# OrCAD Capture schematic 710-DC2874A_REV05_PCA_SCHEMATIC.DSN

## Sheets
1 PAGE4: company: ANALOG DEVICES; note: DEMO BOARD BILL OF MATERIALS; note: 5V, MULTI-PHASE SILENT SWITCHER 2
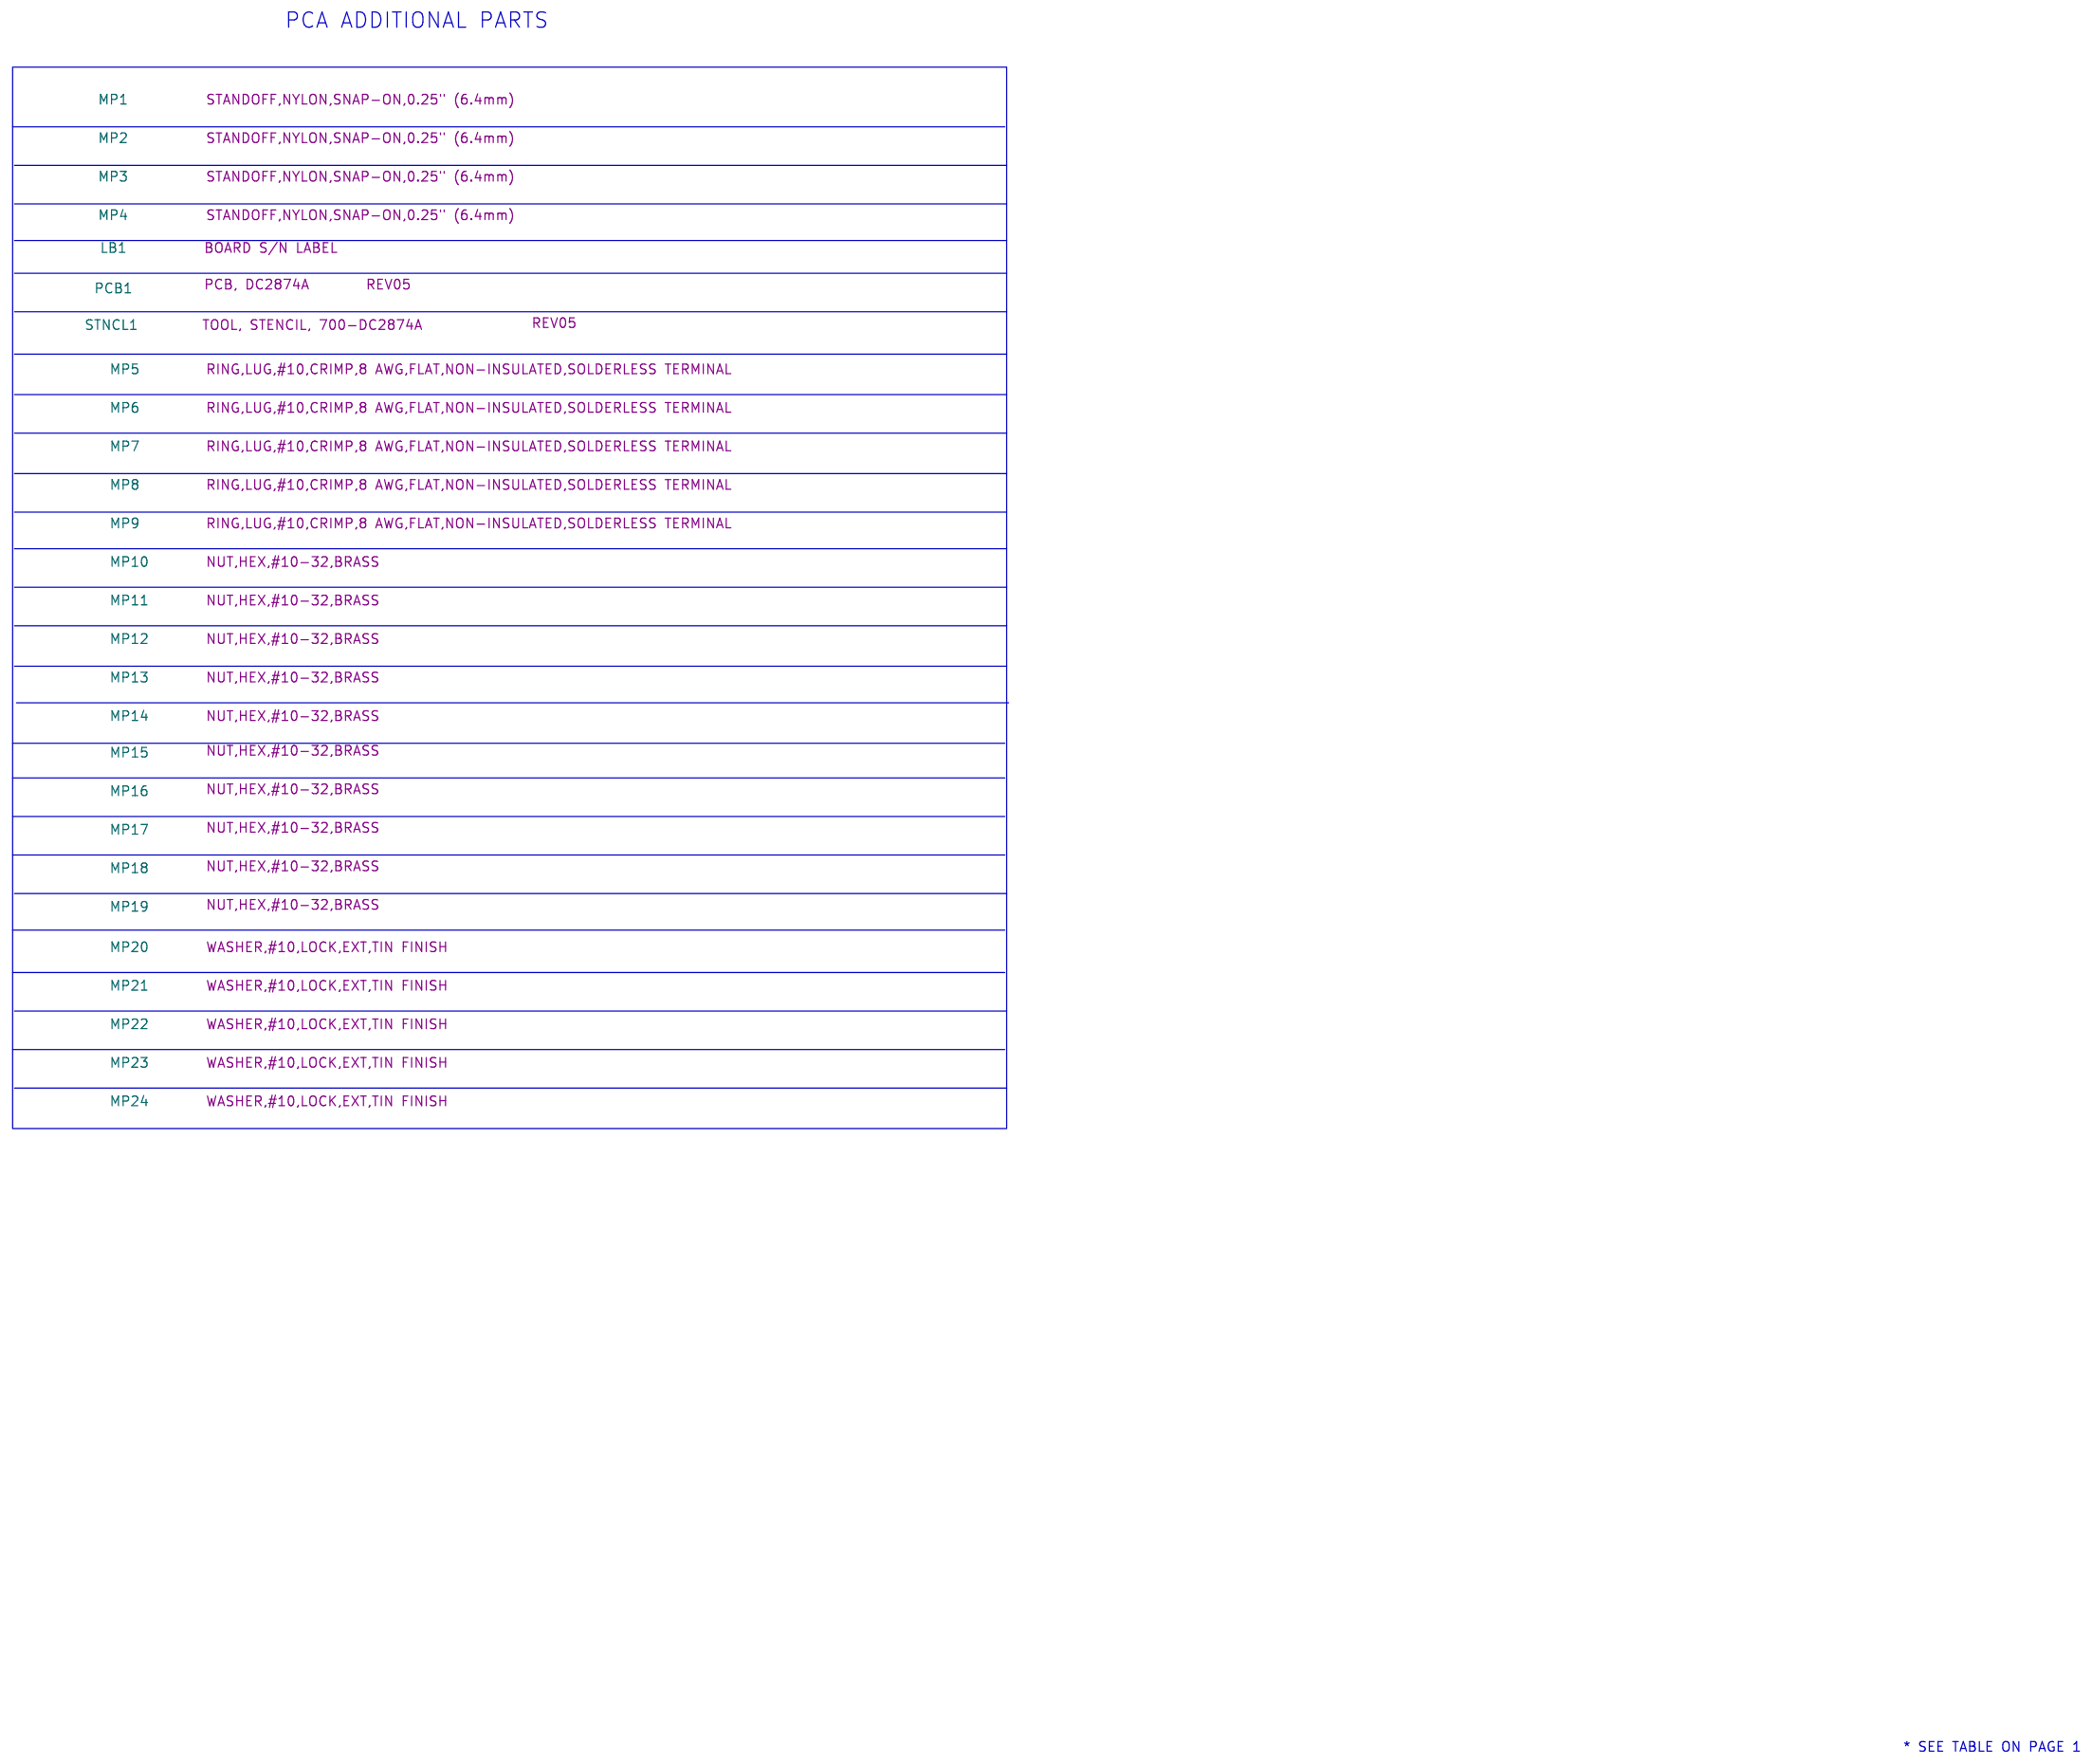
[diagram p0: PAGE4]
2 PAGE3: size B
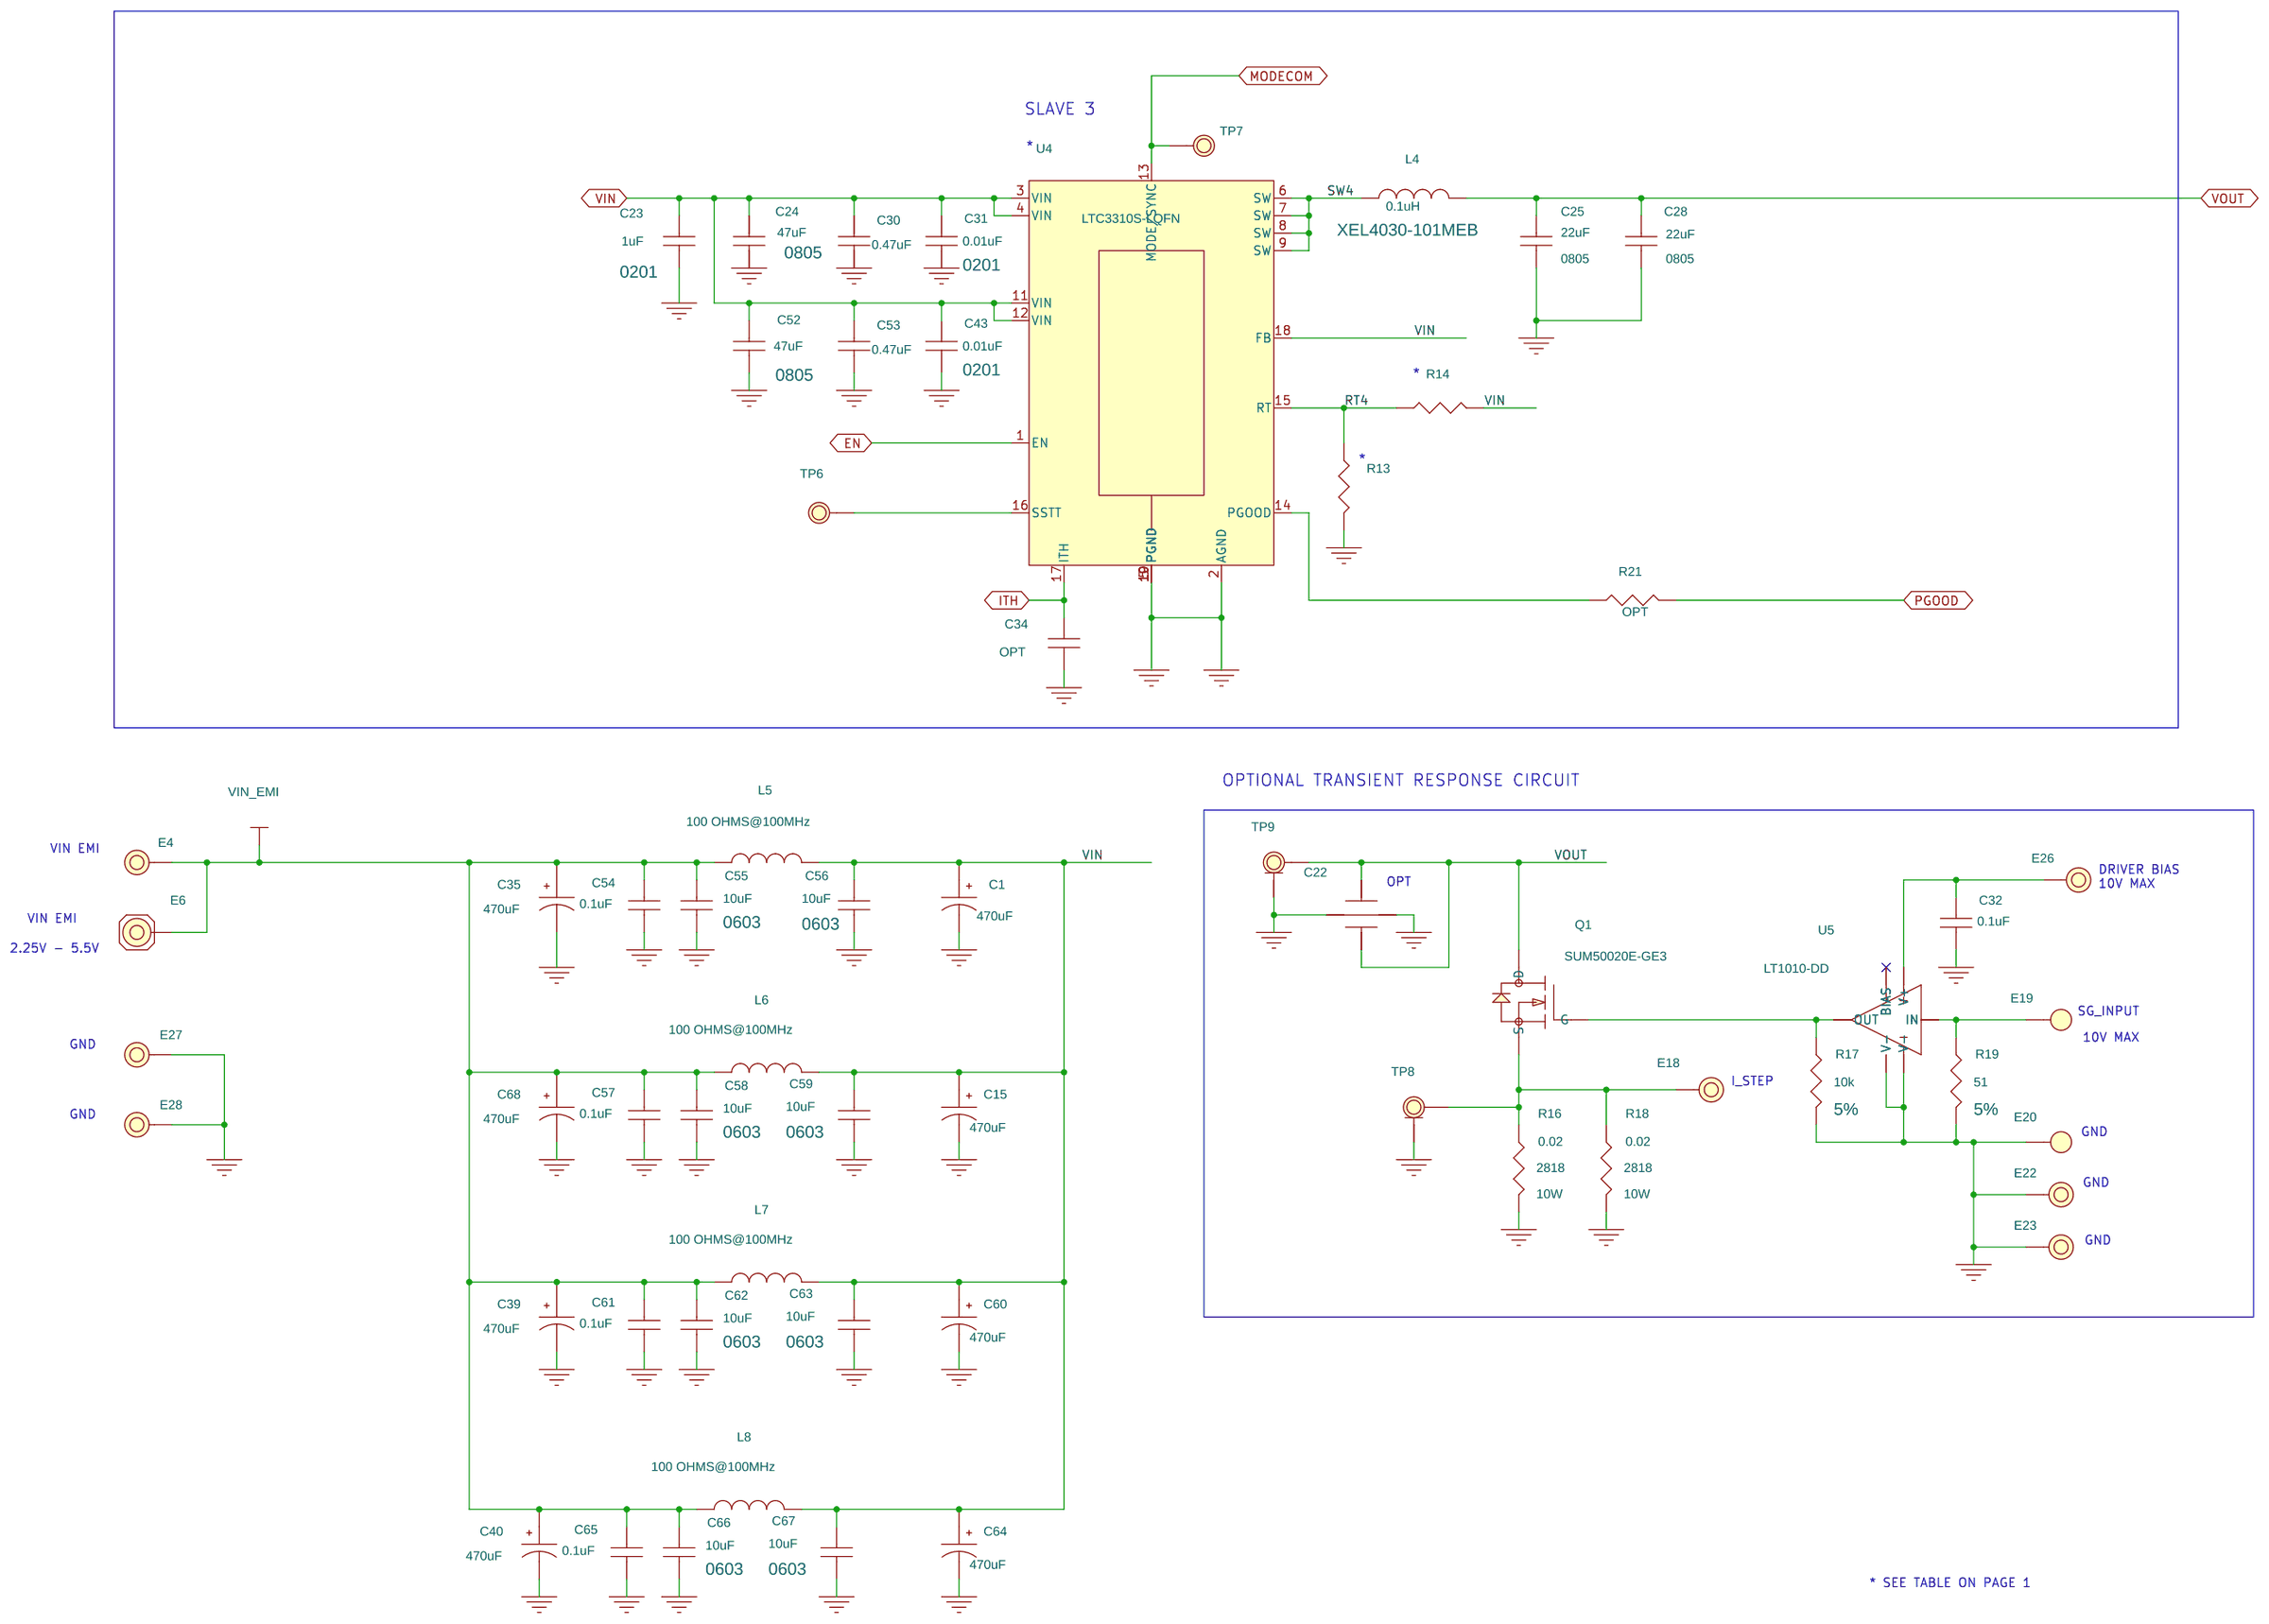
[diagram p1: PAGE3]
3 PAGE2: size B
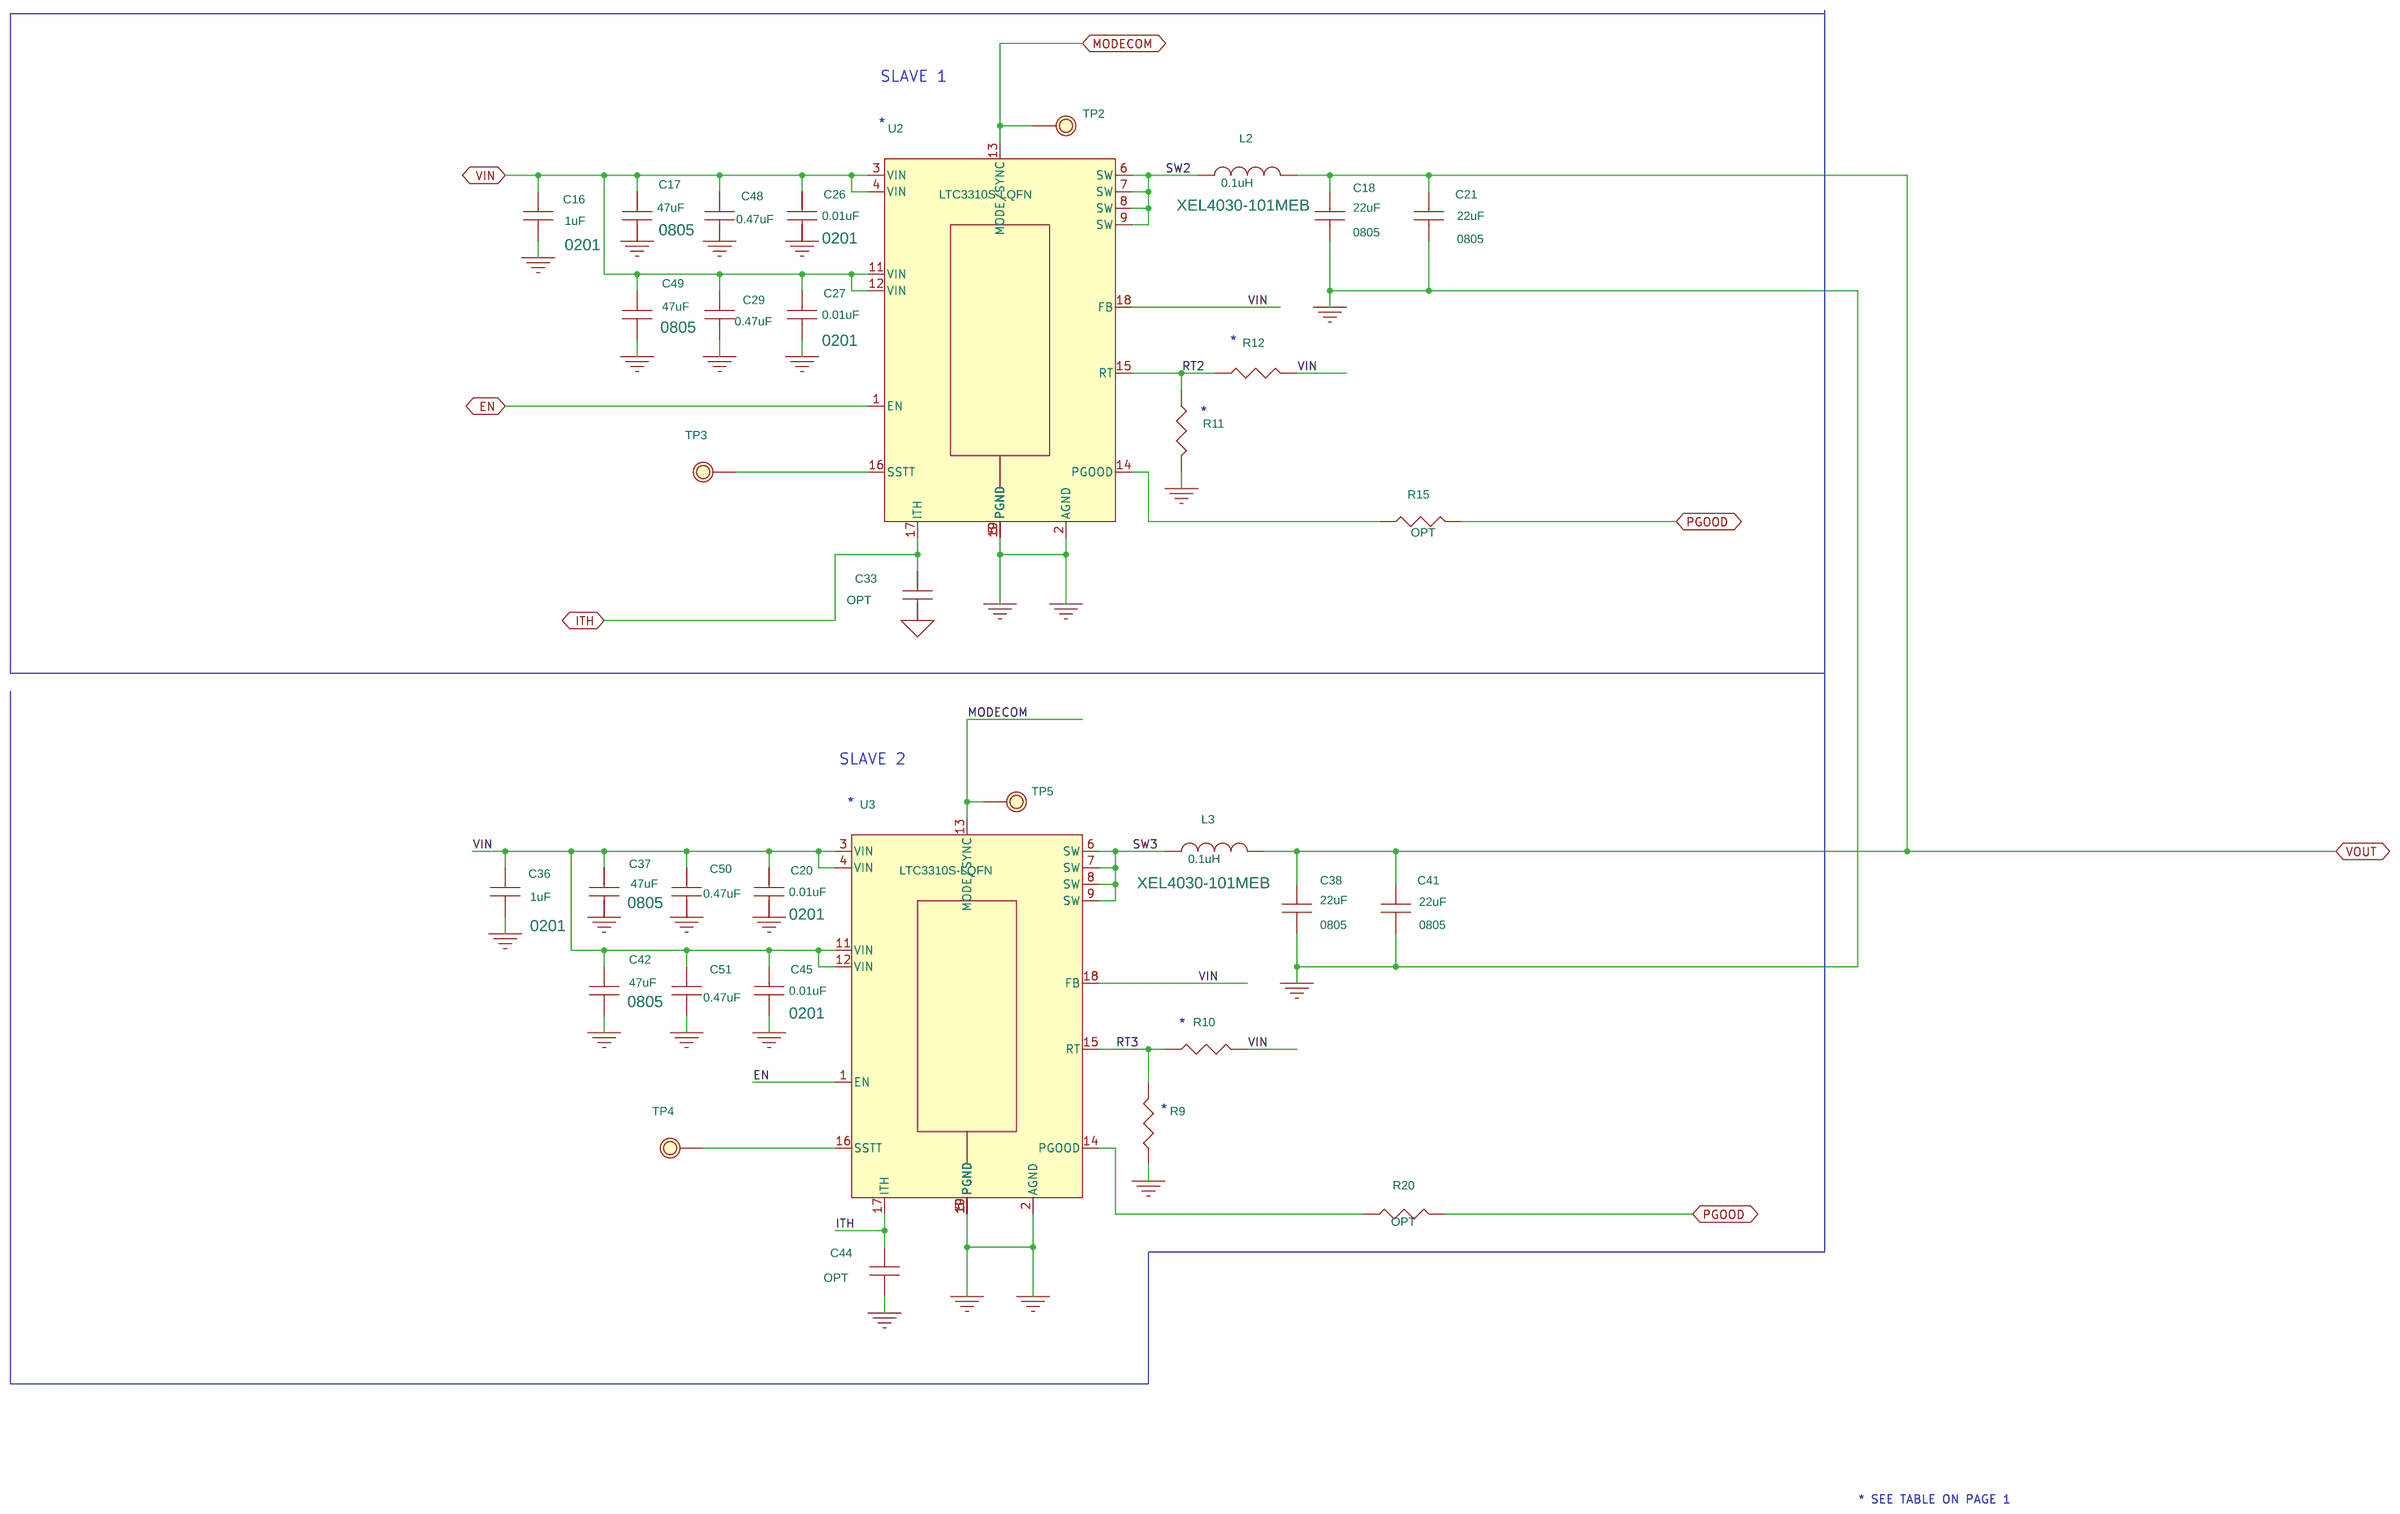
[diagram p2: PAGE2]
4 PAGE1: size B
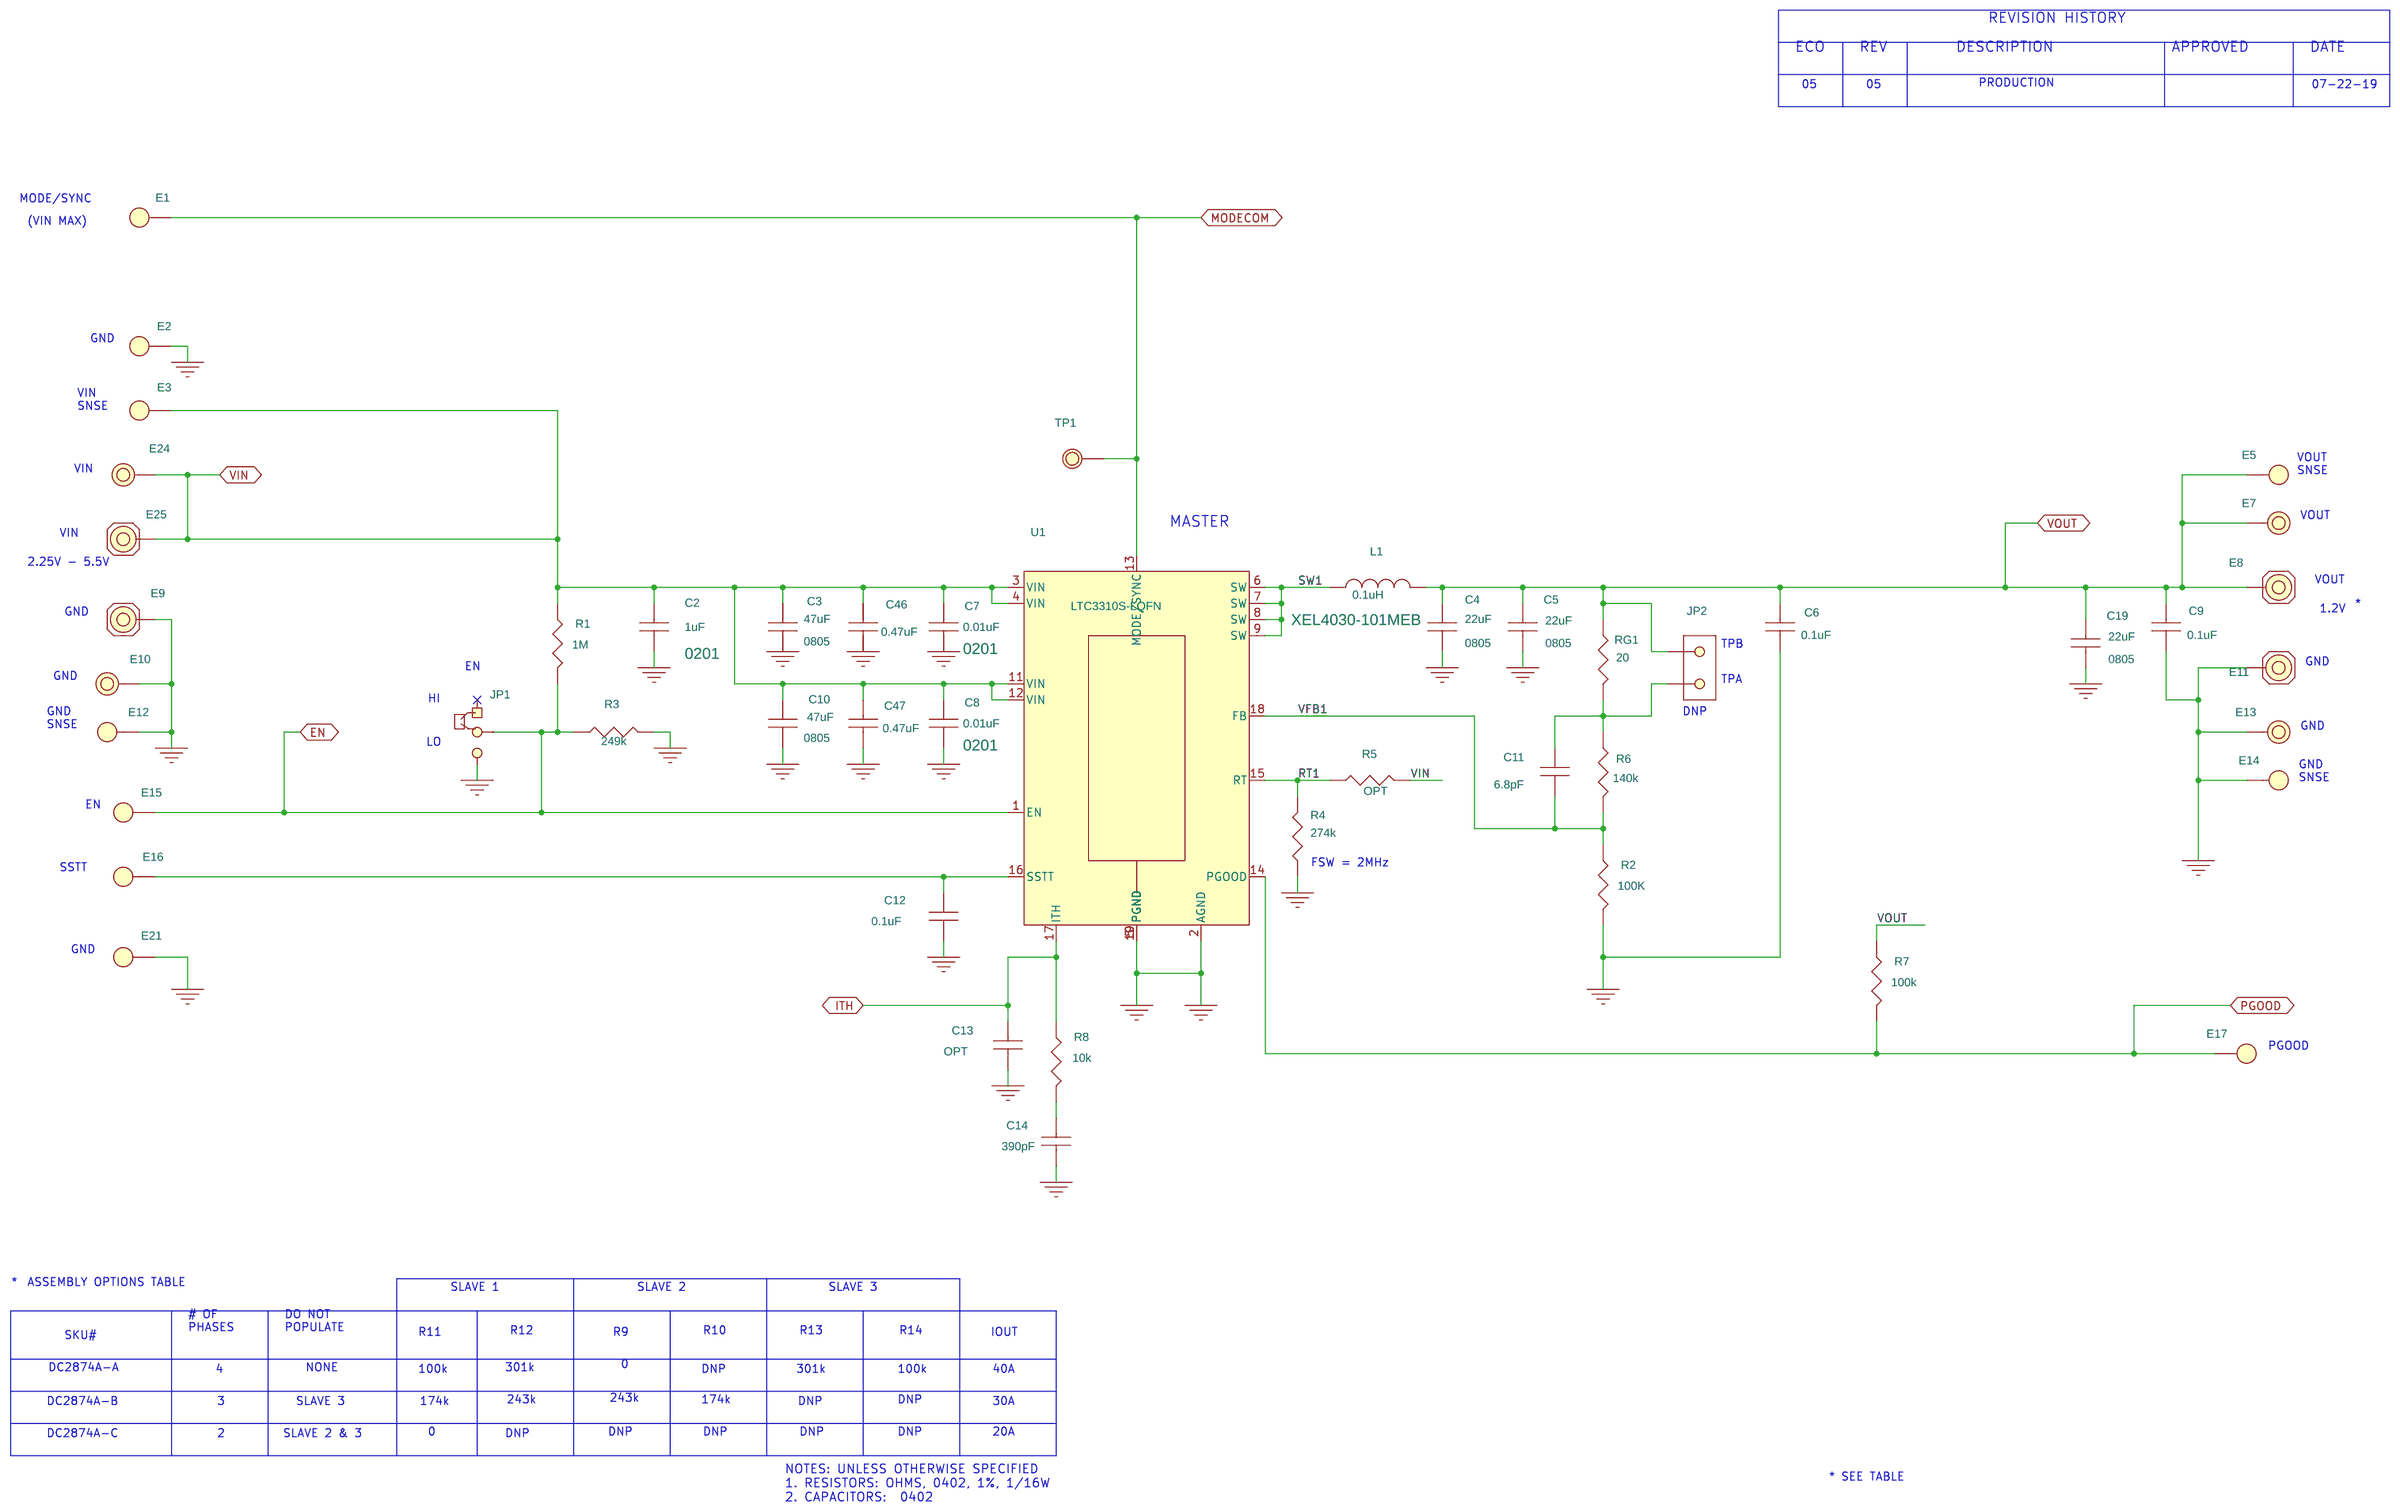
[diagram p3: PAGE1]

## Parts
sheet PAGE1
C2  1uF  [CC0201M]
C3  47uF  [CC0805N]
C4  22uF  [CC0805N]
C5  22uF  [CC0805N]
C6  0.1uF  [CC0402N]
C7  0.01uF  [CC0201M]
C8  0.01uF  [CC0201M]
C9  0.1uF  [CC0402N]
C10  47uF  [CC0805N]
C11  6.8pF  [CC0402N]
C12  0.1uF  [CC0402N]
C13  OPT  [CC0402N]
C14  390pF  [CC0402N]
C19  22uF  [CC0805N]
C46  0.47uF  [CC0402N]
C47  0.47uF  [CC0402N]
E1  TEST POINT  [MILLMAX2308]
E2  TEST POINT  [MILLMAX2308]
E3  TEST POINT  [MILLMAX2308]
E5  TEST POINT  [MILLMAX2308]
E7  TEST POINT  [MILLMAX2501]
E8  STUD  [PENN-KFH-032]
E9  STUD  [PENN-KFH-032]
E10  TEST POINT  [MILLMAX2501]
E11  STUD  [PENN-KFH-032]
E12  TEST POINT  [MILLMAX2308]
E13  TEST POINT  [MILLMAX2501]
E14  TEST POINT  [MILLMAX2308]
E15  TEST POINT  [MILLMAX2308]
E16  TEST POINT  [MILLMAX2308]
E17  TEST POINT  [MILLMAX2308]
E21  TEST POINT  [MILLMAX2308]
E24  TEST POINT  [MILLMAX2501]
E25  STUD  [PENN-KFH-032]
JP1  HDR  [HD1X3-079]
JP2  HDR  [HD1X2-079]
L1  0.1uH  [COILCRAFT-XEL4030]
R1  1M  [CR0402N]
R2  100K  [CR0402N]
R3  249k  [CR0402N]
R4  274k  [CR0402N]
R5  OPT  [CR0402N]
R6  140k  [CR0402N]
R7  100k  [CR0402N]
R8  10k  [CR0402N]
RG1  20  [CR0402N]
TP1  TEST PAD  [PADSTYLE2]
U1  LTC3310S-LQFN  [LTC-LQFN-18-1548]
XJP1  SHUNT
sheet PAGE2
C16  1uF  [CC0201M]
C17  47uF  [CC0805N]
C18  22uF  [CC0805N]
C20  0.01uF  [CC0201M]
C21  22uF  [CC0805N]
C26  0.01uF  [CC0201M]
C27  0.01uF  [CC0201M]
C29  0.47uF  [CC0402N]
C33  OPT  [CC0402N]
C36  1uF  [CC0201M]
C37  47uF  [CC0805N]
C38  22uF  [CC0805N]
C41  22uF  [CC0805N]
C42  47uF  [CC0805N]
C44  OPT  [CC0402N]
C45  0.01uF  [CC0201M]
C48  0.47uF  [CC0402N]
C49  47uF  [CC0805N]
C50  0.47uF  [CC0402N]
C51  0.47uF  [CC0402N]
L2  0.1uH  [COILCRAFT-XEL4030]
L3  0.1uH  [COILCRAFT-XEL4030]
R9  0  [CR0402N]
R10  OPT  [CR0402N]
R11  100K  [CR0402N]
R12  301k  [CR0402N]
R15  OPT  [CR0402N]
R20  OPT  [CR0402N]
TP2  TEST PAD  [PADSTYLE2]
TP3  TEST PAD  [PADSTYLE2]
TP4  TEST PAD  [PADSTYLE2]
TP5  TEST PAD  [PADSTYLE2]
U2  LTC3310S-LQFN  [LTC-LQFN-18-1548]
U3  LTC3310S-LQFN  [LTC-LQFN-18-1548]
sheet PAGE3
C1  470uF  [CAPMP7343N]
C15  470uF  [CAPMP7343N]
C22  1000pF  [JOHANSON-X2Y-X07]
C23  1uF  [CC0201M]
C24  47uF  [CC0805N]
C25  22uF  [CC0805N]
C28  22uF  [CC0805N]
C30  0.47uF  [CC0402N]
C31  0.01uF  [CC0201M]
C32  0.1uF  [CC0402N]
C34  OPT  [CC0402N]
C35  470uF  [CAPMP7343N]
C39  470uF  [CAPMP7343N]
C40  470uF  [CAPMP7343N]
C43  0.01uF  [CC0201M]
C52  47uF  [CC0805N]
C53  0.47uF  [CC0402N]
C54  0.1uF  [CC0402N]
C55  10uF  [CC0603N]
C56  10uF  [CC0603N]
C57  0.1uF  [CC0402N]
C58  10uF  [CC0603N]
C59  10uF  [CC0603N]
C60  470uF  [CAPMP7343N]
C61  0.1uF  [CC0402N]
C62  10uF  [CC0603N]
C63  10uF  [CC0603N]
C64  470uF  [CAPMP7343N]
C65  0.1uF  [CC0402N]
C66  10uF  [CC0603N]
C67  10uF  [CC0603N]
C68  470uF  [CAPMP7343N]
E4  TEST POINT  [MILLMAX2501]
E6  STUD  [PENN-KFH-032]
E18  TEST POINT  [MILLMAX2501]
E19  TEST POINT  [MILLMAX2308]
E20  TEST POINT  [MILLMAX2308]
E22  TEST POINT  [MILLMAX2501]
E23  TEST POINT  [MILLMAX2501]
E26  TEST POINT  [MILLMAX2501]
E27  TEST POINT  [MILLMAX2501]
E28  TEST POINT  [MILLMAX2501]
L4  0.1uH  [COILCRAFT-XEL4030]
L5  100 OHMS@100MHz  [WURTH-74279226101]
L6  100 OHMS@100MHz  [WURTH-74279226101]
L7  100 OHMS@100MHz  [WURTH-74279226101]
L8  100 OHMS@100MHz  [WURTH-74279226101]
Q1  SUM50020E-GE3  [VISHAY-TO-263-3]
R13  301k  [CR0402N]
R14  100K  [CR0402N]
R16  0.02  [VISHAY-WSHP2818]
R17  10k  [CR0402N]
R18  0.02  [VISHAY-WSHP2818]
R19  51  [CR0402N]
R21  OPT  [CR0402N]
TP6  TEST PAD  [PADSTYLE2]
TP7  TEST PAD  [PADSTYLE2]
TP8  TEST JACK  [HODEN-PA-652_ALT1]
TP9  TEST JACK  [HODEN-PA-652_ALT1]
U4  LTC3310S-LQFN  [LTC-LQFN-18-1548]
U5  LT1010-DD  [LTC-DD-8-1698]
sheet PAGE4
LB1  LABEL  [895-0154_REV01]
MP1  STANDOFF  [KEYSTONE_8829-8834]
MP2  STANDOFF  [KEYSTONE_8829-8834]
MP3  STANDOFF  [KEYSTONE_8829-8834]
MP4  STANDOFF  [KEYSTONE_8829-8834]
MP5  RING,LUG,#10,CRIMP  [UNASSIGNED]
MP6  RING,LUG,#10,CRIMP  [UNASSIGNED]
MP7  RING,LUG,#10,CRIMP  [UNASSIGNED]
MP8  RING,LUG,#10,CRIMP  [UNASSIGNED]
MP9  RING,LUG,#10,CRIMP  [UNASSIGNED]
MP10  NUT,HEX
MP11  NUT,HEX
MP12  NUT,HEX
MP13  NUT,HEX
MP14  NUT,HEX
MP15  NUT,HEX
MP16  NUT,HEX
MP17  NUT,HEX
MP18  NUT,HEX
MP19  NUT,HEX
MP20  WASHER
MP21  WASHER
MP22  WASHER
MP23  WASHER
MP24  WASHER
PCB1  PCB, DC2874A
STNCL1  TOOL, STENCIL, 700-DC2874A

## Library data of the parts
C2 C16 C23 C36 = CAP: CAP.,1uF,X6S,6.3V,20%,0201; CLASS: DISCRETE; Dielectric Type: X6S; FPLIST: CC0201N,CC0201L,CC0201M; Inventory Qty: 44100; Manufacturer: MURATA; Manufacturer PN: GRM033C80J105ME05D; PART_NUMBER: 150-0777; Package Size: 0201; Rated Voltage: 6.3V; Temperature Coefficient: X6S; Tolerance: 20%
C3 C10 C17 C24 C37 C42 C49 C52 = CAP: CAP.,47uF,X5R,10V,20%,0805; CLASS: DISCRETE; Dielectric Type: X5R; FPLIST: CC0805N,CC0805L,CC0805M; Inventory Qty: 9160; Manufacturer: MURATA; Manufacturer PN: GRM21BR61A476ME15L; PART_NUMBER: 150-0744; Package Size: 0805; Rated Voltage: 10V; Tolerance: 20%
C4 C5 C18 C19 C21 C25 C28 C38 C41 = CAP: CAP.,22uF,X5R,25V,20%,0805; CLASS: DISCRETE; Dielectric Type: X5R; FPLIST: CC0805N,CC0805L,CC0805M; Inventory Qty: 12704; Manufacturer: AVX; Manufacturer PN: 08053D226MAT2A; PART_NUMBER: 150-0068; Package Size: 0805; Rated Voltage: 25V; Tolerance: 20%
C6 C9 C12 C32 C54 C57 C61 C65 = CAP: CAP.,0.1uF,X5R,25V,10%,0402; CLASS: DISCRETE; Dielectric Type: X5R; FPLIST: CC0402N,CC0402L,CC0402M; Inventory Qty: 69552; Manufacturer: AVX; Manufacturer PN: 04023D104KAT2A; PART_NUMBER: 150-0249; Package Size: 0402; Rated Voltage: 25V; Tolerance: 10%
C7 C8 C20 C26 C27 C31 C43 C45 = CAP: CAP.,0.01uF,X7R,6.3V,10%,0201; CLASS: DISCRETE; Dielectric Type: X7R; Inventory Qty: 30155; Manufacturer: MURATA; Manufacturer PN: GRM033R70J103KA01D; PART_NUMBER: 150-0377; Package Size: 0201; Rated Voltage: 6.3V; Tolerance: 10%
C11 = CAP: CAP.,6.8pF,C0G/NP0,50V,+/-0.5pF,0402; CLASS: DISCRETE; Dielectric Type: C0G/NP0; FPLIST: CC0402N,CC0402L,CC0402M; Inventory Qty: 23544; Manufacturer: AVX; Manufacturer PN: 04025A6R8DAT2A; PART_NUMBER: 150-0177; Package Size: 0402; Rated Voltage: 50V; Tolerance: +/-0.5pF
C13 C33 C34 C44 = CAP: CAP., OPTION, 0402; CLASS: DISCRETE; FPLIST: CC0402N,CC0402L,CC0402M; PART_NUMBER: 150-3148; Package Size: 0402; Package Type: SMD
C14 = CAP: CAP.,390pF,COG,50V,5%,0402; CLASS: DISCRETE; Dielectric Type: COG; FPLIST: CC0402N,CC0402L,CC0402M; Inventory Qty: 59676; Manufacturer: AVX; Manufacturer PN: 04025A391JAT2A; PART_NUMBER: 150-0651; Package Size: 0402; Package Type: Surface Mount, MLCC; Rated Voltage: 50V; Temperature Coefficient: C0G, NP0; Tolerance: 5%
C29 C30 C46-C48 C50 C51 C53 = CAP: CAP.,0.47uF,X7S,10V,10%,0402,AEC-Q200; CLASS: DISCRETE; Dielectric Type: X7S; Inventory Qty: 8200; Manufacturer: MURATA; Manufacturer PN: GCM155C71A474KE36D; PART_NUMBER: 150-1786; Package Size: 0402; Package Type: SMD/SMT; Rated Voltage: 10V; Tolerance: 10%
E1-E3 E5 E12 E14-E17 E19-E21 = TEST_POINT_.156_MILL-MAX_2308: TEST POINT,TURRET,0.064" MTG. HOLE,PCB 0.062" THK; CLASS: IO; Inventory Qty: 703428; Manufacturer PN: 2308-2-00-80-00-00-07-0; PART_NUMBER: 260-0004
E4 E7 E10 E13 E22-E24 E26-E28 = TESTPOINT_.219_MILL-MAX_2501: TEST POINT,TURRET,0.094" MTG. HOLE,PCB 0.062" THK; CLASS: IO; Inventory Qty: 399767; Manufacturer: MILL-MAX; Manufacturer PN: 2501-2-00-80-00-00-07-0; PART_NUMBER: 260-0003
E6 E8 E9 E11 E25 = STUD_2: STUD,#10-32,FASTENER,0.625" LENGTH; CLASS: DISCRETE; Inventory Qty: 24555; Manufacturer: PENCOM; Manufacturer PN: PR1422; PART_FIELD_01: <PART_FIELD_01>; PART_FIELD_02: <PART_FIELD_02>; PART_NUMBER: 769-0012
JP1 = 3_PIN_HEADER_.079_SINGLE_ROW_D: CONN.,HDR,MALE,1x3,2mm,VERT,ST,THT; CLASS: IO; Inventory Qty: 25736; Manufacturer: Wurth Elektronik; Manufacturer PN: 62000311121; PART_NUMBER: 250-0484
JP2 = HDR1X2: CONN.,HDR,MALE,1x2,2mm,STR, THT; CLASS: IO; Inventory Qty: 3658; Manufacturer: WURTH ELEKTRONIK; Manufacturer PN: 62000211121; PART_NUMBER: 250-0507
L1-L4 = IND_ALT: IND.,0.1uH,PWR,SHIELDED,20%,25.8A,1.8mOhms,4.3x4.3mm,XEL4030,AEC-Q200; CLASS: DISCRETE; Inventory Qty: 1900; Manufacturer: COILCRAFT; Manufacturer PN: XEL4030-101MEB; PART_NUMBER: 200-0670; Package Size: 4.3x4.3mm,XEL4030; Tolerance: 20%
R1 = RES: RES.,1M OHMS,1%,1/16W,0402,AEC-Q200; CLASS: DISCRETE; FPLIST: CR0402N,CR0402L,CR0402M; Inventory Qty: 90925; Manufacturer: STACKPOLE ELECTRONICS, INC.; Manufacturer PN: RMCF0402FT1M00; PART_NUMBER: 100-2457; Package Size: 0402; Rated Power: 1/16W; Temperature Coefficient: 100ppm; Tolerance: 1%
R2 R11 R14 = RES: RES.,100k OHMS,1%,1/16W,0402,AEC-Q200; CLASS: DISCRETE; FPLIST: CR0402N,CR0402L,CR0402M; Inventory Qty: 92256; Manufacturer: NIC; Manufacturer PN: NRC04F1003TRF; PART_NUMBER: 100-0601; Package Size: 0402; Rated Power: 1/16W; Temperature Coefficient: 100PPM; Tolerance: 1%
R3 = RES: RES.,249k OHMS,1%,1/16W,0402,AEC-Q200; CLASS: DISCRETE; FPLIST: CR0402N,CR0402L,CR0402M; Inventory Qty: 28476; Manufacturer: NIC; Manufacturer PN: NRC04F2493TRF; PART_NUMBER: 100-2663; Package Size: 0402; Rated Power: 1/16W; Temperature Coefficient: 100ppm; Tolerance: 1%
R4 = RES: RES.,274k OHMS,1%,1/16W,0402,AEC-Q200; CLASS: DISCRETE; FPLIST: CR0402N,CR0402L,CR0402M; Inventory Qty: 19490; Manufacturer: NIC; Manufacturer PN: NRC04F2743TRF; PART_NUMBER: 100-2882; Package Size: 0402; Rated Power: 1/16W; Temperature Coefficient: 100ppm; Tolerance: 1%
R5 R10 R15 R20 R21 = RES: RES., OPTION, 0402; CLASS: DISCRETE; FPLIST: CR0402N,CR0402L,CR0402M; PART_NUMBER: 100-0357; Package Size: 0402
R6 = RES: RES.,140k OHMS,1%,1/16W,0402,AEC-Q200; CLASS: DISCRETE; FPLIST: CR0402N,CR0402L,CR0402M; Inventory Qty: 72002; Manufacturer: NIC; Manufacturer PN: NRC04F1403TRF; PART_NUMBER: 100-2880; Package Size: 0402; Rated Power: 1/16W; Temperature Coefficient: 100ppm; Tolerance: 1%
R7 = RES: RES.,100k OHMS,5%,1/16W,0402,AEC-Q200; CLASS: DISCRETE; FPLIST: CR0402N,CR0402L,CR0402M; Inventory Qty: 46910; Manufacturer: NIC; Manufacturer PN: NRC04J104TRF; PART_NUMBER: 100-0359; Package Size: 0402; Rated Power: 1/16W; Temperature Coefficient: 200ppm/C; Tolerance: 5%
R8 = RES: RES.,10k OHMS,1%,1/16W,0402; CLASS: DISCRETE; FPLIST: CR0402N,CR0402L,CR0402M; Inventory Qty: 97536; Manufacturer: SAMSUNG; Manufacturer PN: RC1005F103CS; PART_NUMBER: 100-2314; Package Size: 0402; Rated Power: 1/16W; Temperature Coefficient: 100ppm; Tolerance: 1%
RG1 = RES: RES.,20 OHMS,1%,1/16W,0402,AEC-Q200; CLASS: DISCRETE; FPLIST: CR0402N,CR0402L,CR0402M; Inventory Qty: 32808; Manufacturer: NIC; Manufacturer PN: NRC04F20R0TRF; PART_NUMBER: 100-0250; Package Size: 0402; Rated Power: 1/16W; Temperature Coefficient: 100ppm; Tolerance: 1%
TP1-TP7 = PAD_STYLE_A: TESTPOINT, PCB COPPER FEATURE; CLASS: IO; Manufacturer: N/A; Manufacturer PN: N/A; PART_NUMBER: PCBPADS-1
U1-U4 = LTC3310S-LQFN: IC,Low Voltage Syn. Step-Down Reg,LQFN-18; CLASS: IC; Inventory Qty: 0; Manufacturer: LINEAR TECH.; Manufacturer PN: LTC3310SEV#PBF; PART_NUMBER: LTC3310SEV#PBF; Package Size: 18-LQFN; Package Type: LQFN-18
XJP1 = SHUNT_2MM_D: CONN.,SHUNT,FEMALE,2 POS,2mm; CLASS: IO; Inventory Qty: 71220; Manufacturer: Wurth Elektronik; Manufacturer PN: 60800213421; PART_NUMBER: 250-0485
R9 = RES: RES.,0 OHM,1/16W,0402,AEC-Q200; CLASS: DISCRETE; FPLIST: CR0402N,CR0402L,CR0402M; Inventory Qty: 110914; Manufacturer: NIC; Manufacturer PN: NRC04ZOTRF; PART_NUMBER: 100-2023; Package Size: 0402; Rated Power: 1/16W
R12 R13 = RES: RES.,301k OHMS,1%,1/16W,0402; CLASS: DISCRETE; FPLIST: CR0402N,CR0402L,CR0402M; Inventory Qty: 19800; Manufacturer: SAMSUNG; Manufacturer PN: RC1005F3013CS; PART_NUMBER: 100-0467; Package Size: 0402; Rated Power: 1/16W; Temperature Coefficient: +/-100PPM; Tolerance: 1%
C1 C15 C35 C39 C40 C60 C64 C68 = CAP_P_ALT: CAP.,470uF,TANT,POSCAP,6.3V,20%,7343,18mOHMS,TPE; CLASS: DISCRETE; Dielectric Type: TANT,POSCAP; FPLIST: CAPMP7343N,CAPMP7343L,CAPMP7343M; Inventory Qty: 9212; Manufacturer: PANASONIC; Manufacturer PN: 6TPE470MI; PART_NUMBER: 150-0223; Package Size: 7343; Rated Voltage: 6.3V; Tolerance: 20%
C22 = JOHANSON-X2Y: CAP.,1000pF,X7R,50V,20%,0402,3-TERM,X2Y EMI FILTER; CLASS: DISCRETE; Dielectric Type: X7R; Inventory Qty: 7676; Manufacturer: JOHANSON DIELECTRICS; Manufacturer PN: 500X07W102MV4T; PART_NUMBER: 150-1785; Package Size: 0402,3-TERM; Rated Voltage: 50V; Tolerance: 20%
C55 C56 C58 C59 C62 C63 C66 C67 = CAP: CAP.,10uF,X5R,10V,20%,0603; CLASS: DISCRETE; Dielectric Type: X5R; Inventory Qty: 23275; Manufacturer: AVX; Manufacturer PN: 0603ZD106MAT2A; PART_NUMBER: 150-3459; Package Size: 0603; Package Type: SMD; Rated Voltage: 10V; Tolerance: 20%
E18 = TESTPOINT_.219_MILL-MAX_2501: TEST POINT,TURRET,0.094" MTG. HOLE,PCB 0.062" THK; CLASS: IO; FPLIST: MILLMAX2501,MILLMAX2501_ALT1; Inventory Qty: 399767; Manufacturer: MILL-MAX; Manufacturer PN: 2501-2-00-80-00-00-07-0; PART_NUMBER: 260-0003
L5-L8 = IND_ALT: IND.,100 OHMS@100MHz,FERRITE BEAD,25%,8A,6mOHMS,1812; CLASS: DISCRETE; Inventory Qty: 1842; Manufacturer: WURTH ELEKTRONIK; Manufacturer PN: 74279226101; PART_NUMBER: 200-0280; Package Size: 1812; Tolerance: 25%
Q1 = 3P_N-CH_TYPE2A: XSTR.,MOSFET, N-CH,60V,120A,TO-263; CLASS: DISCRETE; Inventory Qty: 535; Manufacturer: VISHAY; PART_NUMBER: 240-0407; Package Size: TO-263-3, D²Pak (2 Leads + Tab), TO-263AB; Package Type: TO-263; Polarity: N-Channel; Rated Voltage: 60V
R16 R18 = RES: RES.,0.02 OHM,1%,10W,2818,HP,METAL,SENSE,AEC-Q200; CLASS: DISCRETE; Inventory Qty: 2900; Manufacturer: VISHAY; Manufacturer PN: WSHP2818R0200FEA; PART_NUMBER: 100-1320; Package Size: 2818; Rated Power: 10W; Temperature Coefficient: +/-75ppm; Tolerance: 1%
R17 = RES: RES.,10k OHMS,5%,1/16W,0402,AEC-Q200; CLASS: DISCRETE; Inventory Qty: 70192; Manufacturer: NIC; Manufacturer PN: NRC04J103TRF; PART_NUMBER: 100-0214; Package Size: 0402; Rated Power: 1/16W; Temperature Coefficient: 200ppm; Tolerance: 5%
R19 = RES: RES.,51 OHMS,5%,1/16W,0402,AEC-Q200; CLASS: DISCRETE; FPLIST: CR0402N,CR0402L,CR0402M; Inventory Qty: 21313; Manufacturer: NIC; Manufacturer PN: NRC04J510TRF; PART_NUMBER: 100-0367; Package Size: 0402; Rated Power: 1/16W; Temperature Coefficient: 200ppm/C; Tolerance: 5%
TP8 TP9 = HODEN_TEST_JACK_PK5-2.5MM-113_1: CONN.,TEST JACK,PLUG,VERT. THT,SHIELDED, 1 POS; CLASS: IO; FPLIST: HODEN-PA-652, HODEN-PA-652_ALT1; Manufacturer: HODEN ELECTRONICS CO; Manufacturer PN: PK5-2.5MM-113; PART_NUMBER: TMP-3717
U5 = LT1010-DD: IC,OPAMP BUFFER,20MHz,+/-150mA,DFN-8; CLASS: IC; Inventory Qty: 605; Manufacturer: LINEAR TECH.; Manufacturer PN: LT1010CDD#PBF; PART_NUMBER: LT1010CDD#PBF; Package Size: 8-WFDFN Exposed Pad; Package Type: DFN-8
LB1 = BLANK_LABEL: LABEL SPEC, DEMO BOARD SERIAL NUMBER; Inventory Qty: 0; Manufacturer: BRADY; Manufacturer PN: THT-96-717-10; PART_FIELD_01: BOARD S/N LABEL; PART_NUMBER: 895-0154
MP1-MP4 = BLANK_MECHANICAL_PART: STANDOFF,NYLON,SNAP-ON,0.25" (6.4mm); CLASS: DISCRETE; Inventory Qty: 185444; Manufacturer: KEYSTONE; Manufacturer PN: 8831; PART_NUMBER: 763-0006
MP5-MP9 = BLANK_MECHANICAL_PART: RING,LUG,#10,CRIMP,8 AWG,FLAT,NON-INSULATED,SOLDERLESS TERMINAL; CLASS: DISCRETE; Inventory Qty: 3500; Manufacturer: Molex; Manufacturer PN: 0192210223; PART_NUMBER: 769-0018
MP10-MP19 = BLANK_PINLESS_MECHANICAL_PART: NUT,HEX,#10-32,BRASS; CLASS: DISCRETE; Inventory Qty: 43114; Manufacturer: PENCOM; Manufacturer PN: NU1132; PART_NUMBER: 761-0013
MP20-MP24 = BLANK_PINLESS_MECHANICAL_PART: WASHER,#10,LOCK,EXT,TIN FINISH; CLASS: DISCRETE; Inventory Qty: 20345; Manufacturer: PENCOM; Manufacturer PN: WA4526; PART_NUMBER: 762-0021
PCB1 = BLANK_PCB_PART: BOM Notes: REV05; CLASS: DISCRETE; Inventory Qty: 0; Manufacturer: EAGLE TECH. INC.; Manufacturer PN: 600-DC2874A; PART_NUMBER: 600-DC2874A
STNCL1 = BLANK_STENCIL_PART: BOM Notes: REV05; CLASS: DISCRETE; Inventory Qty: 0; Manufacturer: LINEAR TECH.; Manufacturer PN: 830-DC2874A; PART_NUMBER: 830-DC2874A

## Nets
GND: C1.2 C2.2 C3.2 C4.2 C5.2 C6.2 C7.2 C8.2 C9.2 C10.2 C12.2 C13.2 C14.2 C15.2 C16.2 C17.2 C18.2 C19.2 C20.2 C21.2 C22.3(G1) C22.4(G2) C23.2 C24.2 C25.2 C26.2 C27.2 C28.2 C29.2 C30.2 C31.2 C32.2 C33.2 C34.2 C35.2 C36.2 C37.2 C38.2 C39.2 C40.2 C41.2 C42.2 C43.2 C44.2 C45.2 C46.2 C47.2 C48.2 C49.2 C50.2 C51.2 C52.2 C53.2 C54.2 C55.2 C56.2 C57.2 C58.2 C59.2 C60.2 C61.2 C62.2 C63.2 C64.2 C65.2 C66.2 C67.2 C68.2 E2.1(A) E9.1 E10.1 E11.1 E12.1(A) E13.1 E14.1(A) E20.1(A) E21.1(A) E22.1 E23.1 E27.1 E28.1 JP1.3 R2.2 R3.2 R4.1 R9.1 R11.2 R13.2 R16.2 R17.2 R18.2 R19.2 TP8.2(GND) TP8.3(GND) TP8.4(GND) TP8.5(GND) TP9.2(GND) TP9.3(GND) TP9.4(GND) TP9.5(GND) U1.2(AGND) U1.5(PGND) U1.10(PGND) U1.19(PGND) U2.2(AGND) U2.5(PGND) U2.10(PGND) U2.19(PGND) U3.2(AGND) U3.5(PGND) U3.10(PGND) U3.19(PGND) U4.2(AGND) U4.5(PGND) U4.10(PGND) U4.19(PGND) U5.6(V-) U5.9(V-)
VIN: C1.1 C2.1 C3.1 C7.1 C8.1 C10.1 C15.1 C16.1 C17.1 C20.1 C23.1 C24.1 C26.1 C27.1 C29.1 C30.1 C31.1 C36.1 C37.1 C42.1 C43.1 C45.1 C46.1 C47.1 C48.1 C49.1 C50.1 C51.1 C52.1 C53.1 C56.1 C59.1 C60.1 C63.1 C64.1 C67.1 E3.1(A) E24.1 E25.1 L5.2 L6.2 L7.2 L8.2 R1.1 R5.2 R10.2 R12.2 R14.2 U1.3(VIN) U1.4(VIN) U1.11(VIN) U1.12(VIN) U2.3(VIN) U2.4(VIN) U2.11(VIN) U2.12(VIN) U2.18(FB) U3.3(VIN) U3.4(VIN) U3.11(VIN) U3.12(VIN) U3.18(FB) U4.3(VIN) U4.4(VIN) U4.11(VIN) U4.12(VIN) U4.18(FB)
VIN_EMI: C35.1 C39.1 C40.1 C54.1 C55.1 C57.1 C58.1 C61.1 C62.1 C65.1 C66.1 C68.1 E4.1 E6.1 L5.1 L6.1 L7.1 L8.1
EN: E15.1(A) JP1.2 R1.2 R3.1 U1.1(EN) U2.1(EN) U3.1(EN) U4.1(EN)
ITH: C13.1 C33.1 C34.1 C44.1 R8.1 U1.17(ITH) U2.17(ITH) U3.17(ITH) U4.17(ITH)
MODECOM: E1.1(A) TP1.1 TP2.1 TP5.1 TP7.1 U1.13(MODE/SYNC) U2.13(MODE/SYNC) U3.13(MODE/SYNC) U4.13(MODE/SYNC)
PGOOD: E17.1(A) R7.2 R15.2 R20.2 R21.2 U1.14(PGOOD)
RT1: R4.2 R5.1 U1.15(RT)
RT2: R11.1 R12.1 U2.15(RT)
RT3: R9.2 R10.1 U3.15(RT)
RT4: R13.1 R14.1 U4.15(RT)
SW1: L1.1 U1.6(SW) U1.7(SW) U1.8(SW) U1.9(SW)
SW2: L2.1 U2.6(SW) U2.7(SW) U2.8(SW) U2.9(SW)
SW3: L3.1 U3.6(SW) U3.7(SW) U3.8(SW) U3.9(SW)
SW4: L4.1 U4.6(SW) U4.7(SW) U4.8(SW) U4.9(SW)
VFB1: C11.2 R2.1 R6.2 U1.18(FB)
VOUT: C4.1 C5.1 C6.1 C9.1 C18.1 C19.1 C21.1 C22.1(A) C22.2(B) C25.1 C28.1 C38.1 C41.1 E5.1(A) E7.1 E8.1 JP2.1 L1.2 L2.2 L3.2 L4.2 Q1.2(D) R7.1 RG1.1 TP9.1
N16696136: C11.1 JP2.2 R6.1 RG1.2
N16696210: C14.1 R8.2
N16696796: C12.1 E16.1(A) U1.16(SSTT)
N16701112: TP3.1 U2.16(SSTT)
N16704455: TP4.1 U3.16(SSTT)
N16817046: TP6.1 U4.16(SSTT)
N16859410: E19.1(A) R19.1 U5.8(IN)
N16859415: E18.1 Q1.3(S) R16.1 R18.1 TP8.1
N16986734: R15.1 U2.14(PGOOD)
N16986825: R20.1 U3.14(PGOOD)
N16986889: R21.1 U4.14(PGOOD)
N17011780: Q1.1(G) R17.1 U5.3(OUT)
N17012743: C32.1 E26.1 U5.1(V+)

Not connected (* = marked no-connect by the designer): JP1 1*; U5 2(BIAS)*

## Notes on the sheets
sheet 1
- PCA ADDITIONAL PARTS
- * SEE TABLE ON PAGE 1
sheet 2
- SLAVE 3
- *
- *
- *
- OPTIONAL TRANSIENT RESPONSE CIRCUIT
- VIN EMI
- OPT
- DRIVER BIAS
  10V MAX
- VIN EMI
- 2.25V - 5.5V
- SG_INPUT
- GND
- 10V MAX
- I_STEP
- GND
- GND
- GND
- GND
- * SEE TABLE ON PAGE 1
sheet 3
- SLAVE 1
- *
- *
- *
- SLAVE 2
- *
- *
- *
- * SEE TABLE ON PAGE 1
sheet 4
- REVISION HISTORY
- ECO
- REV
- DESCRIPTION
- APPROVED
- DATE
- 05
- 05
- PRODUCTION
- 07-22-19
- MODE/SYNC
- (VIN MAX)
- GND
- VIN
  SNSE
- VIN
- VOUT
  SNSE
- MASTER
- VOUT
- VIN
- 2.25V - 5.5V
- VOUT
- 1.2V
- *
- GND
- TPB
- GND
- GND
- EN
- TPA
- HI
- GND
  SNSE
- DNP
- GND
- LO
- GND
  SNSE
- EN
- SSTT
- FSW = 2MHz
- GND
- PGOOD
- *
- ASSEMBLY OPTIONS TABLE
- SLAVE 1
- SLAVE 2
- SLAVE 3
- # OF
  PHASES
- DO NOT
  POPULATE
- SKU#
- R11
- R12
- R9
- R10
- R13
- R14
- IOUT
- DC2874A-A
- NONE
- 301k
- 0
- 4
- 100k
- DNP
- 301k
- 100k
- 40A
- DC2874A-B
- 3
- SLAVE 3
- 174k
- 243k
- 243k
- 174k
- DNP
- DNP
- 30A
- DC2874A-C
- 2
- SLAVE 2 & 3
- 0
- DNP
- DNP
- DNP
- DNP
- DNP
- 20A
- NOTES: UNLESS OTHERWISE SPECIFIED
  1. RESISTORS: OHMS, 0402, 1%, 1/16W
  2. CAPACITORS:  0402
- * SEE TABLE
